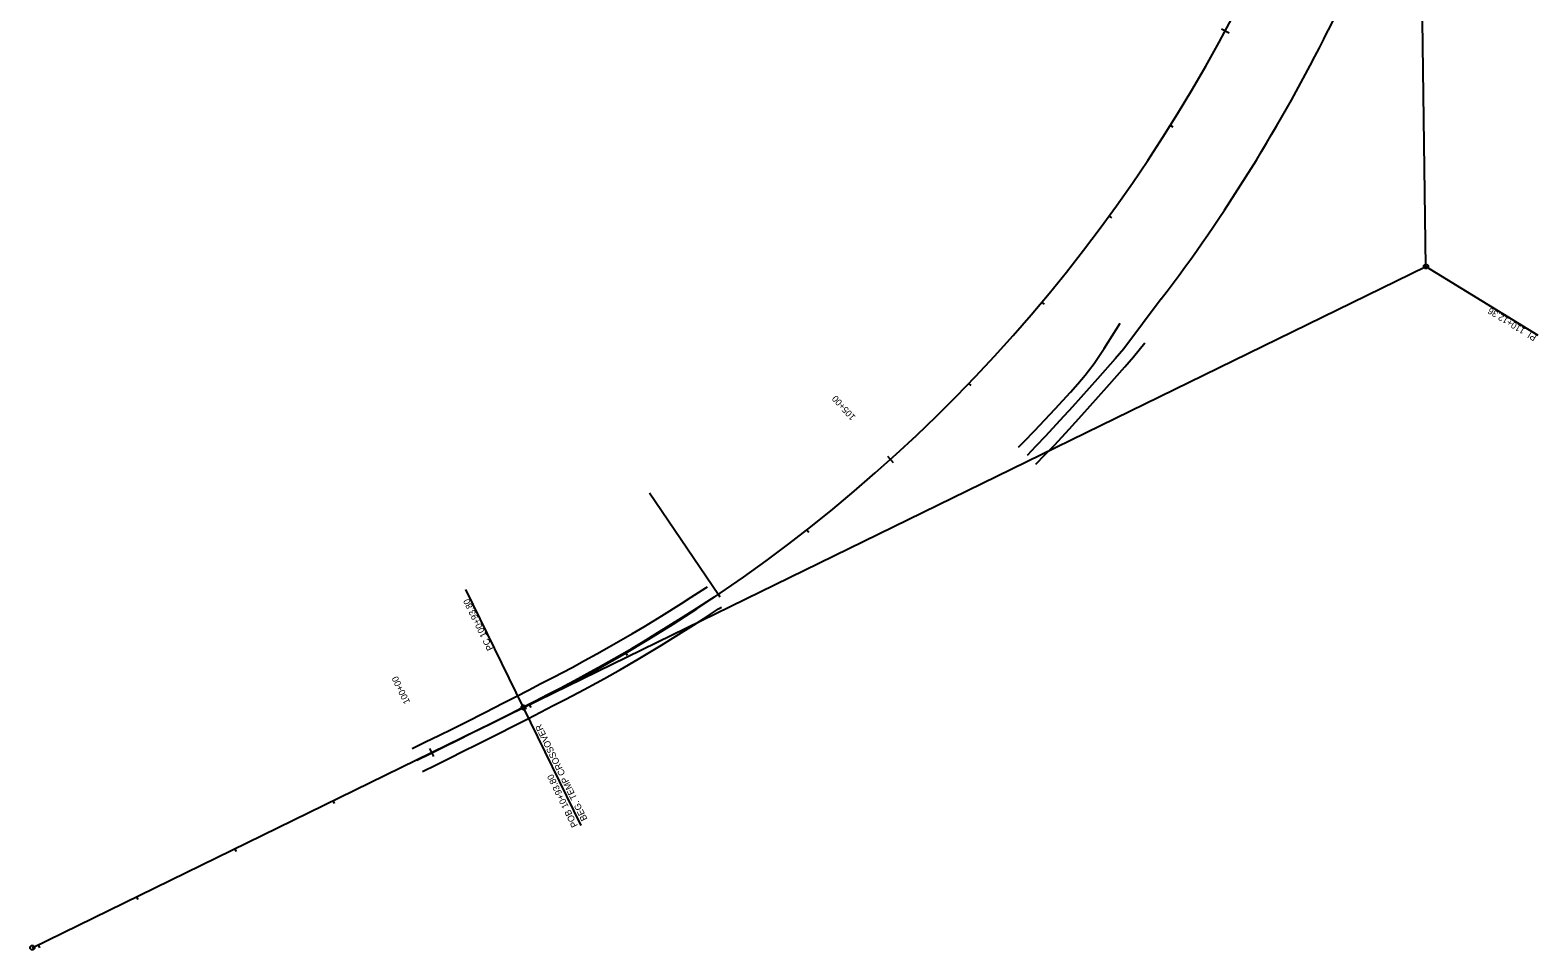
# Model space of a CAD drawing. Extents: x 1665984 to 1683035, y 227465 to 233856.
# Drawn here: x 1676114 to 1677492, y 227465 to 228306 of the extents above; entities that cross this region are included whole.
import ezdxf

# ---------------------------------------------------------------- set-up
doc = ezdxf.new("R2010")
doc.units = 0
for name, color, linetype in [('R_Horz Alg', 7, 'Continuous'), ('R_Horz Alg Annot', 7, 'Continuous'), ('R_Striping', 7, 'Continuous')]:
    doc.layers.add(name, color=color, linetype=linetype)

msp = doc.modelspace()

# ---------------------------------------------------------------- linework, layer by layer
at = {"layer": 'R_Horz Alg'}
msp.add_line((1676115.6, 227467.2), (1676564.8, 227686.9), dxfattribs=at)
msp.add_arc((1675928.2, 228988.5), 1449, 296.0624, 0.8056, dxfattribs=at)
at = {"layer": 'R_Horz Alg Annot'}
for p, q in [((1677389.9, 228090.4), (1677377, 229008.9)), ((1676564.8, 227686.9), (1677389.9, 228090.4)), ((1676679.8, 227883.2), (1676742.9, 227790.3))]:
    msp.add_line(p, q, dxfattribs=at)
for points in [[(1677202.8, 228307.8), (1677209.8, 228304)], [(1677158.7, 228217.8), (1677156.2, 228219.4)], [(1677102.7, 228134.8), (1677100.2, 228136.6)], [(1677389.9, 228090.4), (1677492.2, 228027.6)], [(1677041, 228055.8), (1677038.7, 228057.8)], [(1676974, 227981.3), (1676971.9, 227983.4)], [(1676897.4, 227916.8), (1676902.7, 227910.9)], [(1676825.5, 227847), (1676823.6, 227849.4)], [(1676564.8, 227686.9), (1676512.1, 227794.7)], [(1676744.6, 227787.8), (1676742.9, 227790.3)], [(1676659.9, 227734.4), (1676658.4, 227737)], [(1676617.5, 227579.1), (1676564.8, 227686.9)], [(1676571.7, 227686.9), (1676570.3, 227689.6)], [(1676478.8, 227649.3), (1676482.3, 227642.1)], [(1676392, 227599), (1676390.7, 227601.7)], [(1676302.2, 227555.1), (1676300.9, 227557.8)], [(1676212.3, 227511.2), (1676211, 227513.9)], [(1676122.5, 227467.2), (1676121.2, 227469.9)]]:
    msp.add_lwpolyline(points, dxfattribs=at)
for centre in [(1677389.9, 228090.4), (1676564.8, 227686.9), (1676115.6, 227467.2)]:
    msp.add_circle(centre, 2, dxfattribs=at)
at = {"layer": 'R_Striping'}
for points in [[(1677309.5, 228325.2), (1677300.6, 228306.5)], [(1677147.8, 228060.6), (1677113.7, 228015.1), (1677105.8, 228005.9), (1677089.5, 227987.6), (1677081.8, 227979), (1677066.6, 227961.9), (1677055.2, 227949.3), (1677042.1, 227935.1), (1677033.2, 227925.8), (1677025.1, 227917.5)], [(1677017.4, 227924.9), (1677022.5, 227930.1), (1677032, 227940), (1677041.4, 227950.1), (1677050.8, 227960.1), (1677064.8, 227975.2), (1677071.7, 227983), (1677078.3, 227990.9), (1677081.4, 227994.9), (1677086.4, 228001.6), (1677089.6, 228006.1), (1677095.7, 228015.4), (1677110.4, 228038.6)], [(1677033.3, 227909.4), (1677041.5, 227917.9), (1677050.5, 227927.3), (1677063.7, 227941.5), (1677075.2, 227954.3), (1677090.4, 227971.4), (1677098, 227979.9), (1677114.5, 227998.4), (1677122.5, 228007.7), (1677132.9, 228020.5)], [(1676463, 227649.4), (1676475.2, 227655.4), (1676487.4, 227661.4), (1676499.7, 227667.4), (1676511.9, 227673.4), (1676529.2, 227682.3), (1676546.5, 227691.1), (1676557.9, 227697), (1676569.3, 227702.9), (1676580.7, 227708.8), (1676592.1, 227714.6), (1676609.2, 227723.6), (1676620.6, 227729.8), (1676631.8, 227736), (1676643.1, 227742.3), (1676664.5, 227754.7), (1676675.2, 227761), (1676691.1, 227770.7), (1676709.1, 227782), (1676718.1, 227787.7), (1676731.5, 227796.5), (1676732.9, 227797.4)], [(1676467.2, 227638.6), (1676479.6, 227644.8), (1676492, 227651), (1676504.4, 227657.1), (1676516.8, 227663.3), (1676534.4, 227672.1), (1676552, 227680.9), (1676563.5, 227686.8), (1676575, 227692.8), (1676586.6, 227698.8), (1676598.1, 227704.7), (1676614.8, 227713.5), (1676625.8, 227719.5), (1676633.1, 227723.5), (1676647.6, 227731.7), (1676663.7, 227741), (1676674.4, 227747.4), (1676685, 227753.9), (1676695.6, 227760.3), (1676714, 227771.9), (1676723.2, 227777.7), (1676736.8, 227786.6), (1676739.2, 227788.2)], [(1676472.4, 227628.3), (1676484.8, 227634.5), (1676497.1, 227640.7), (1676509.5, 227646.8), (1676521.9, 227653), (1676539.6, 227661.8), (1676557.2, 227670.6), (1676568.8, 227676.6), (1676580.3, 227682.6), (1676591.9, 227688.6), (1676603.4, 227694.5), (1676620.2, 227703.4), (1676631.3, 227709.4), (1676638.7, 227713.4), (1676653.3, 227721.7), (1676669.5, 227731.1), (1676680.3, 227737.5), (1676691, 227744), (1676701.7, 227750.6), (1676720.2, 227762.2), (1676729.4, 227768.1), (1676743.1, 227777), (1676745.6, 227778.6)]]:
    msp.add_lwpolyline(points, dxfattribs=at)
msp.add_arc((1675928.2, 228988.5), 1532.5, 322.7359, 333.5741, dxfattribs=at)

# ---------------------------------------------------------------- texts
at = {"layer": 'R_Horz Alg Annot'}
for s, rotation, p in [('PI  110+12.36', 148.434, (1677491.6, 228026.8)), ('105+00', 132.1242, (1676868.7, 227952.9)), ('PC 100+93.80', 116.0624, (1676537.3, 227740.7)), ('100+00', 116.0624, (1676461.2, 227691.9)), ('BEG. TEMP CROSSOVER', 116.0624, (1676623.3, 227584.9)), ('POB 10+93.80', 116.0624, (1676614.6, 227579))]:
    msp.add_text(s, height=6, rotation=rotation, dxfattribs=at).set_placement(p)

doc.saveas('drawing.dxf')
